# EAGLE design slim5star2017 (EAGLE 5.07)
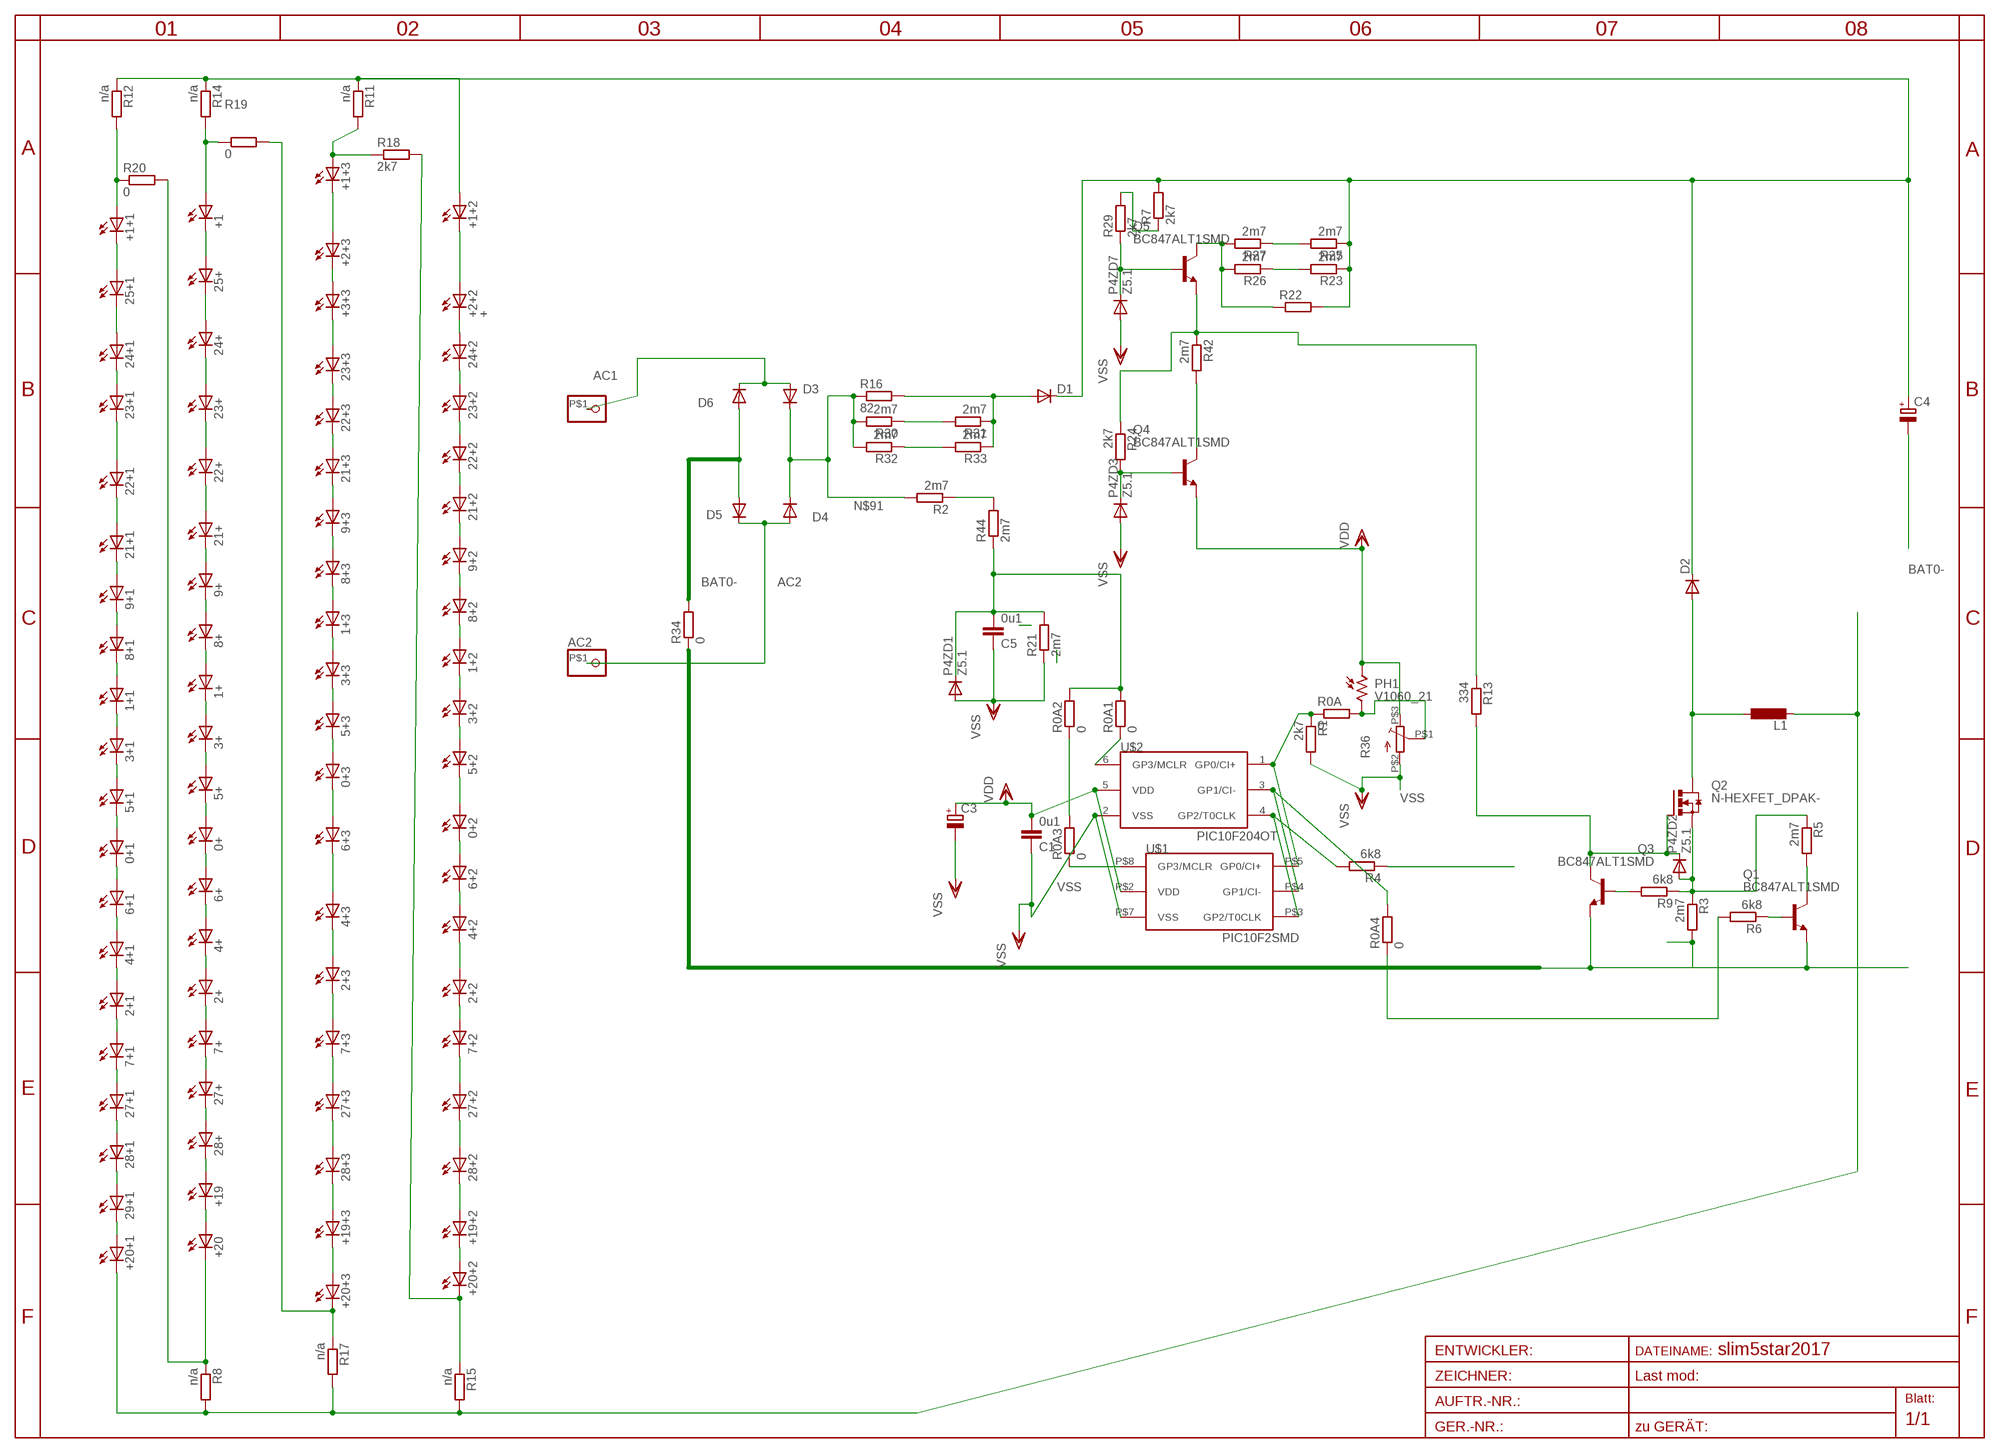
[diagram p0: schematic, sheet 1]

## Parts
0+  LED1210  [1210]
0+1  LED1210  [1210]
0+2  LED1210  [1210]
0+3  LED1210  [1210]
1+  LED1210  [1210]
1+1  LED1210  [1210]
1+2  LED1210  [1210]
1+3  LED1210  [1210]
2+  LED1210  [1210]
2+1  LED1210  [1210]
2+2  LED1210  [1210]
2+3  LED1210  [1210]
3+  LED1210  [1210]
3+1  LED1210  [1210]
3+2  LED1210  [1210]
3+3  LED1210  [1210]
4+  LED1210  [1210]
4+1  LED1210  [1210]
4+2  LED1210  [1210]
4+3  LED1210  [1210]
5+  LED1210  [1210]
5+1  LED1210  [1210]
5+2  LED1210  [1210]
5+3  LED1210  [1210]
6+  LED1210  [1210]
6+1  LED1210  [1210]
6+2  LED1210  [1210]
6+3  LED1210  [1210]
7+  LED1210  [1210]
7+1  LED1210  [1210]
7+2  LED1210  [1210]
7+3  LED1210  [1210]
8+  LED1210  [1210]
8+1  LED1210  [1210]
8+2  LED1210  [1210]
8+3  LED1210  [1210]
9+  LED1210  [1210]
9+1  LED1210  [1210]
9+2  LED1210  [1210]
9+3  LED1210  [1210]
21+  LED1210  [1210]
21+1  LED1210  [1210]
21+2  LED1210  [1210]
21+3  LED1210  [1210]
22+  LED1210  [1210]
22+1  LED1210  [1210]
22+2  LED1210  [1210]
22+3  LED1210  [1210]
23+  LED1210  [1210]
23+1  LED1210  [1210]
23+2  LED1210  [1210]
23+3  LED1210  [1210]
24+  LED1210  [1210]
24+1  LED1210  [1210]
24+2  LED1210  [1210]
25+  LED1210  [1210]
25+1  LED1210  [1210]
27+  LED1210  [1210]
27+1  LED1210  [1210]
27+2  LED1210  [1210]
27+3  LED1210  [1210]
28+  LED1210  [1210]
28+1  LED1210  [1210]
28+2  LED1210  [1210]
28+3  LED1210  [1210]
29+1  LED1210  [1210]
+1  LED1210  [1210]
+1+1  LED1210  [1210]
+1+2  LED1210  [1210]
+1+3  LED1210  [1210]
+2+2  +  LED1210  [1210]
+2+3  LED1210  [1210]
+3+3  LED1210  [1210]
+19  LED1210  [1210]
+19+2  LED1210  [1210]
+19+3  LED1210  [1210]
+20  LED1210  [1210]
+20+1  LED1210  [1210]
+20+2  LED1210  [1210]
+20+3  LED1210  [1210]
AC1  PINHD-1X1SMD  [SMD1X1]
AC2  PINHD-1X1SMD  [SMD1X1]
C1  0u1  C-EUC1206  [C1206]
C3  CPOL-EUE  [PANASONIC_E]
C4  CPOL-EUSANYO_SMD_F12  [SANYO-OSCON_SMD_F12]
C5  0u1  C-EUC1206  [C1206]
D1  DIODE-SMA-DO214  [SMA-DO214AC]
D2  DIODE-SMC  [SMC]
D3  DIODE-SOD80C  [SOD80C]
D4  DIODE-SOD80C  [SOD80C]
D5  DIODE-SOD80C  [SOD80C]
D6  DIODE-SOD80C  [SOD80C]
L1  L-EUPIS2816  [PIS2816]
P4ZD1  Z5.1  DIODE-MINIMELF  [MINIMELF]
P4ZD2  Z5.1  DIODE-MINIMELF  [MINIMELF]
P4ZD3  Z5.1  DIODE-MINIMELF  [MINIMELF]
P4ZD7  Z5.1  DIODE-MINIMELF  [MINIMELF]
PH1  V1060_21  [TO-5_V10]
Q1  BC847ALT1SMD  [SOT23]
Q2  N-HEXFET_DPAK-  [TO252]
Q3  BC847ALT1SMD  [SOT23]
Q4  BC847ALT1SMD  [SOT23]
Q5  BC847ALT1SMD  [SOT23]
R0A  0  R-EU_R1206  [R1206]
R0A1  0  R-EU_R1206  [R1206]
R0A2  0  R-EU_R1206  [R1206]
R0A3  0  R-EU_R1206  [R1206]
R0A4  0  R-EU_R1206  [R1206]
R1  2k7  R-EU_R0805  [R0805]
R2  2m7  R-EU_R1210  [R1210]
R3  2m7  R-EU_R1206  [R1206]
R4  6k8  R-EU_R0805  [R0805]
R5  2m7  R-EU_R1210  [R1210]
R6  6k8  R-EU_R1206  [R1206]
R7  2k7  R-EU_R0805  [R0805]
R8  n/a  R-EU_R0402  [R0402]
R9  6k8  R-EU_R1206  [R1206]
R11  n/a  R-EU_R0402  [R0402]
R12  n/a  R-EU_R0402  [R0402]
R13  334  R-EU_R0805  [R0805]
R14  n/a  R-EU_R0402  [R0402]
R15  n/a  R-EU_R0402  [R0402]
R16  82  R-EU_SMD15  [SMDCARB15]
R17  n/a  R-EU_R0402  [R0402]
R18  2k7  R-EU_R0402  [R0402]
R19  0  R-EU_R0402  [R0402]
R20  0  R-EU_R0402  [R0402]
R21  2m7  R-EU_R0805  [R0805]
R22  R-EU_SMD15  [SMDCARB15]
R23  2m7  R-EU_R1210  [R1210]
R24  2k7  R-EU_R1206  [R1206]
R25  2m7  R-EU_R1210  [R1210]
R26  2m7  R-EU_R1210  [R1210]
R27  2m7  R-EU_R1210  [R1210]
R29  2k7  R-EU_R0805  [R0805]
R30  2m7  R-EU_R1210  [R1210]
R31  2m7  R-EU_R1210  [R1210]
R32  2m7  R-EU_R1210  [R1210]
R33  2m7  R-EU_R1210  [R1210]
R34  0  R-EU_R1206  [R1206]
R36  TRIM_EU-SMD6A  [CA6VSMD]
R42  2m7  R-EU_R1206  [R1206]
R44  2m7  R-EU_R1210  [R1210]
U$1  PIC10F2SMD  [DIL8SMD]
U$2  PIC10F204OT  [SOT23-6]

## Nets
AC1: Q5.2(E) R13.1 R24.1 R42.1
AC2: AC2.P$1 D4.A D5.C
BAT0-: C4.- D5.A D6.A R34.2
BATT-: Q1.2(E) Q3.2(E) R3.2 R34.1
D: D2.A L1.1 Q2.3(D)
D+: +1+2.P$1(A) C4.+ D1.K(C) D2.C R7.2 R11.1 R12.1 R14.1 R22.P$2 R23.1 R25.1
MINUS: +20+1.P$2(C) L1.2 R8.2 R15.2 R17.2
N$1: +1+3.P$1(A) R11.2 R18.1
N$2: +1+1.P$1(A) R12.2 R20.1
N$4: +20+3.P$2(C) R17.1 R19.2
N$5: Q4.3(C) R42.2
N$6: 8+.P$1(A) 9+.P$2(C)
N$7: +19.P$2(C) +20.P$1(A)
N$8: 28+.P$2(C) +19.P$1(A)
N$9: 27+.P$2(C) 28+.P$1(A)
N$10: 29+1.P$2(C) +20+1.P$1(A)
N$11: 28+1.P$2(C) 29+1.P$1(A)
N$12: 2+.P$2(C) 7+.P$1(A)
N$13: 7+.P$2(C) 27+.P$1(A)
N$14: 2+.P$1(A) 4+.P$2(C)
N$15: 4+.P$1(A) 6+.P$2(C)
N$16: 0+.P$2(C) 6+.P$1(A)
N$17: 0+.P$1(A) 5+.P$2(C)
N$18: 3+.P$2(C) 5+.P$1(A)
N$19: 1+.P$2(C) 3+.P$1(A)
N$20: 1+.P$1(A) 8+.P$2(C)
N$21: 27+1.P$2(C) 28+1.P$1(A)
N$22: 2+1.P$1(A) 4+1.P$2(C)
N$23: 9+.P$1(A) 21+.P$2(C)
N$24: 21+.P$1(A) 22+.P$2(C)
N$25: 22+.P$1(A) 23+.P$2(C)
N$26: 24+.P$1(A) 25+.P$2(C)
N$27: 25+.P$1(A) +1.P$2(C)
N$28: 23+.P$1(A) 24+.P$2(C)
N$29: 4+1.P$1(A) 6+1.P$2(C)
N$30: 0+1.P$2(C) 6+1.P$1(A)
N$31: 0+1.P$1(A) 5+1.P$2(C)
N$32: 3+1.P$2(C) 5+1.P$1(A)
N$33: 1+1.P$2(C) 3+1.P$1(A)
N$34: 1+1.P$1(A) 8+1.P$2(C)
N$35: 9+1.P$1(A) 21+1.P$2(C)
N$36: 21+1.P$1(A) 22+1.P$2(C)
N$37: 22+1.P$1(A) 23+1.P$2(C)
N$38: 25+1.P$1(A) +1+1.P$2(C)
N$39: 24+1.P$1(A) 25+1.P$2(C)
N$40: 23+1.P$1(A) 24+1.P$2(C)
N$41: 2+1.P$2(C) 7+1.P$1(A)
N$42: 7+1.P$2(C) 27+1.P$1(A)
N$43: 8+1.P$1(A) 9+1.P$2(C)
N$45: +1.P$1(A) R14.2 R19.1
N$46: +19+2.P$2(C) +20+2.P$1(A)
N$47: 28+2.P$2(C) +19+2.P$1(A)
N$48: 27+2.P$2(C) 28+2.P$1(A)
N$49: 2+2.P$1(A) 4+2.P$2(C)
N$50: 4+2.P$1(A) 6+2.P$2(C)
N$51: 0+2.P$2(C) 6+2.P$1(A)
N$52: 0+2.P$1(A) 5+2.P$2(C)
N$53: 3+2.P$2(C) 5+2.P$1(A)
N$54: 1+2.P$2(C) 3+2.P$1(A)
N$55: 1+2.P$1(A) 8+2.P$2(C)
N$56: 9+2.P$1(A) 21+2.P$2(C)
N$57: 21+2.P$1(A) 22+2.P$2(C)
N$58: 22+2.P$1(A) 23+2.P$2(C)
N$59: +1+2.P$2(C) +2+2.P$1(A)
N$60: 24+2.P$1(A) +2+2.P$2(C)
N$61: 23+2.P$1(A) 24+2.P$2(C)
N$62: 2+2.P$2(C) 7+2.P$1(A)
N$63: 7+2.P$2(C) 27+2.P$1(A)
N$64: 8+2.P$1(A) 9+2.P$2(C)
N$65: +20+2.P$2(C) R15.1 R18.2
N$66: +20.P$2(C) R8.1 R20.2
N$67: +19+3.P$2(C) +20+3.P$1(A)
N$68: 28+3.P$2(C) +19+3.P$1(A)
N$69: 27+3.P$2(C) 28+3.P$1(A)
N$70: 2+3.P$1(A) 4+3.P$2(C)
N$71: 4+3.P$1(A) 6+3.P$2(C)
N$72: 0+3.P$2(C) 6+3.P$1(A)
N$73: 0+3.P$1(A) 5+3.P$2(C)
N$74: 3+3.P$2(C) 5+3.P$1(A)
N$75: 1+3.P$2(C) 3+3.P$1(A)
N$76: 1+3.P$1(A) 8+3.P$2(C)
N$77: 9+3.P$1(A) 21+3.P$2(C)
N$78: 21+3.P$1(A) 22+3.P$2(C)
N$79: 22+3.P$1(A) 23+3.P$2(C)
N$80: +1+3.P$2(C) +2+3.P$1(A)
N$81: +2+3.P$2(C) +3+3.P$1(A)
N$82: 23+3.P$1(A) +3+3.P$2(C)
N$83: 2+3.P$2(C) 7+3.P$1(A)
N$84: 7+3.P$2(C) 27+3.P$1(A)
N$85: 8+3.P$1(A) 9+3.P$2(C)
N$86: D1.A R16.P$2 R31.1 R33.1
N$88: PH1.2 R0A.2 R36.P$1(S)
N$91: D3.C D4.C R2.2 R16.P$1 R30.2 R32.2
N$92: Q5.3(C) R22.P$1 R26.2 R27.2
N$93: AC1.P$1 D3.A D6.C
N$94: P4ZD2.C Q2.1(G) Q3.3(C) R13.2
N$95: R4.2 U$1.P$3(GP2/T0CLK) U$2.4(GP2/T0CLK)
N$96: C5.2 P4ZD1.C R0A1.2 R0A2.2 R21.2 R44.1
N$97: R2.1 R44.2
N$98: Q1.1(B) R6.1
N$99: R23.2 R26.1
N$100: R25.2 R27.1
N$101: Q1.3(C) R5.2
N$102: R0A4.1 R6.2
N$103: P4ZD3.C Q4.1(B) R24.2
N$104: P4ZD7.C Q5.1(B) R29.1
N$105: P4ZD2.A Q2.2(S) R3.1 R5.1 R9.1
N$106: R7.1 R29.2
N$107: R30.1 R31.2
N$108: R32.1 R33.2
N$109: Q3.1(B) R9.2
N$110: R0A.1 R1.1 U$1.P$5(GP0/CI+) U$2.1(GP0/CI+)
N$111: R0A2.1 R0A3.2
N$112: R0A3.1 U$1.P$8(GP3/MCLR)
N$113: R0A1.1 U$2.6(GP3/MCLR)
N$114: R0A4.2 U$1.P$4(GP1/CI-) U$2.3(GP1/CI-)
PIR: R4.1
VDD: C1.2 C3.+ PH1.1 Q4.2(E) R36.P$3(E) U$1.P$2(VDD) U$2.5(VDD)
VSS: C1.1 C3.- C5.1 P4ZD1.A P4ZD3.A P4ZD7.A R1.2 R21.1 R36.P$2(A) U$1.P$7(VSS) U$2.2(VSS)

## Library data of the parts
0+ 0+1-0+3 1+ 1+1-1+3 2+ 2+1-2+3 3+ 3+1-3+3 4+ 4+1-4+3 5+ 5+1-5+3 6+ 6+1-6+3 7+ 7+1-7+3 8+ 8+1-8+3 9+ 9+1-9+3 21+ 21+1-21+3 22+ 22+1-22+3 23+ 23+1-23+3 24+ 24+1 24+2 25+ 25+1 27+ 27+1-27+3 28+ 28+1-28+3 29+1 +1 +1+1-+1+3 +2+2 +2+3 +3+3 +19 +19+2 +19+3 +20 +20+1-+20+3 = led(2):LED: LED
AC1 AC2 = pinhead:PINHD-1X1: PIN HEADER
C1 C5 = rcl:C-EU: CAPACITOR, European symbol
C3 C4 = rcl-2:CPOL-EU: POLARIZED CAPACITOR, European symbol
D1-D6 P4ZD1-P4ZD3 P4ZD7 = diode:DIODE-: DIODE
L1 = rcl:L-EU: INDUCTOR, European symbol
PH1 = photo-elements:?1060*: Sensor Street Light control
Q1 Q3-Q5 = transistor-npn:BC847*: NPN Transistor
Q2 = transistor-power:N-HEXFET_?-*: HEXFET® Power MOSFET
R0A R0A1-R0A4 R1-R7 R9 R13 R16 R21-R23 R25-R27 R29-R34 R42 R44 = rcl:R-EU_: RESISTOR, European symbol
R8 R11 R12 R14 R15 R17-R20 R24 = rcl-2:R-EU_: RESISTOR, European symbol
R36 = pot:TRIM_EU-: POTENTIOMETER
U$1 U$2 = microchip-5:PIC10F2*: uPC nW 0,25/0,5k Program Flash memory Comparator

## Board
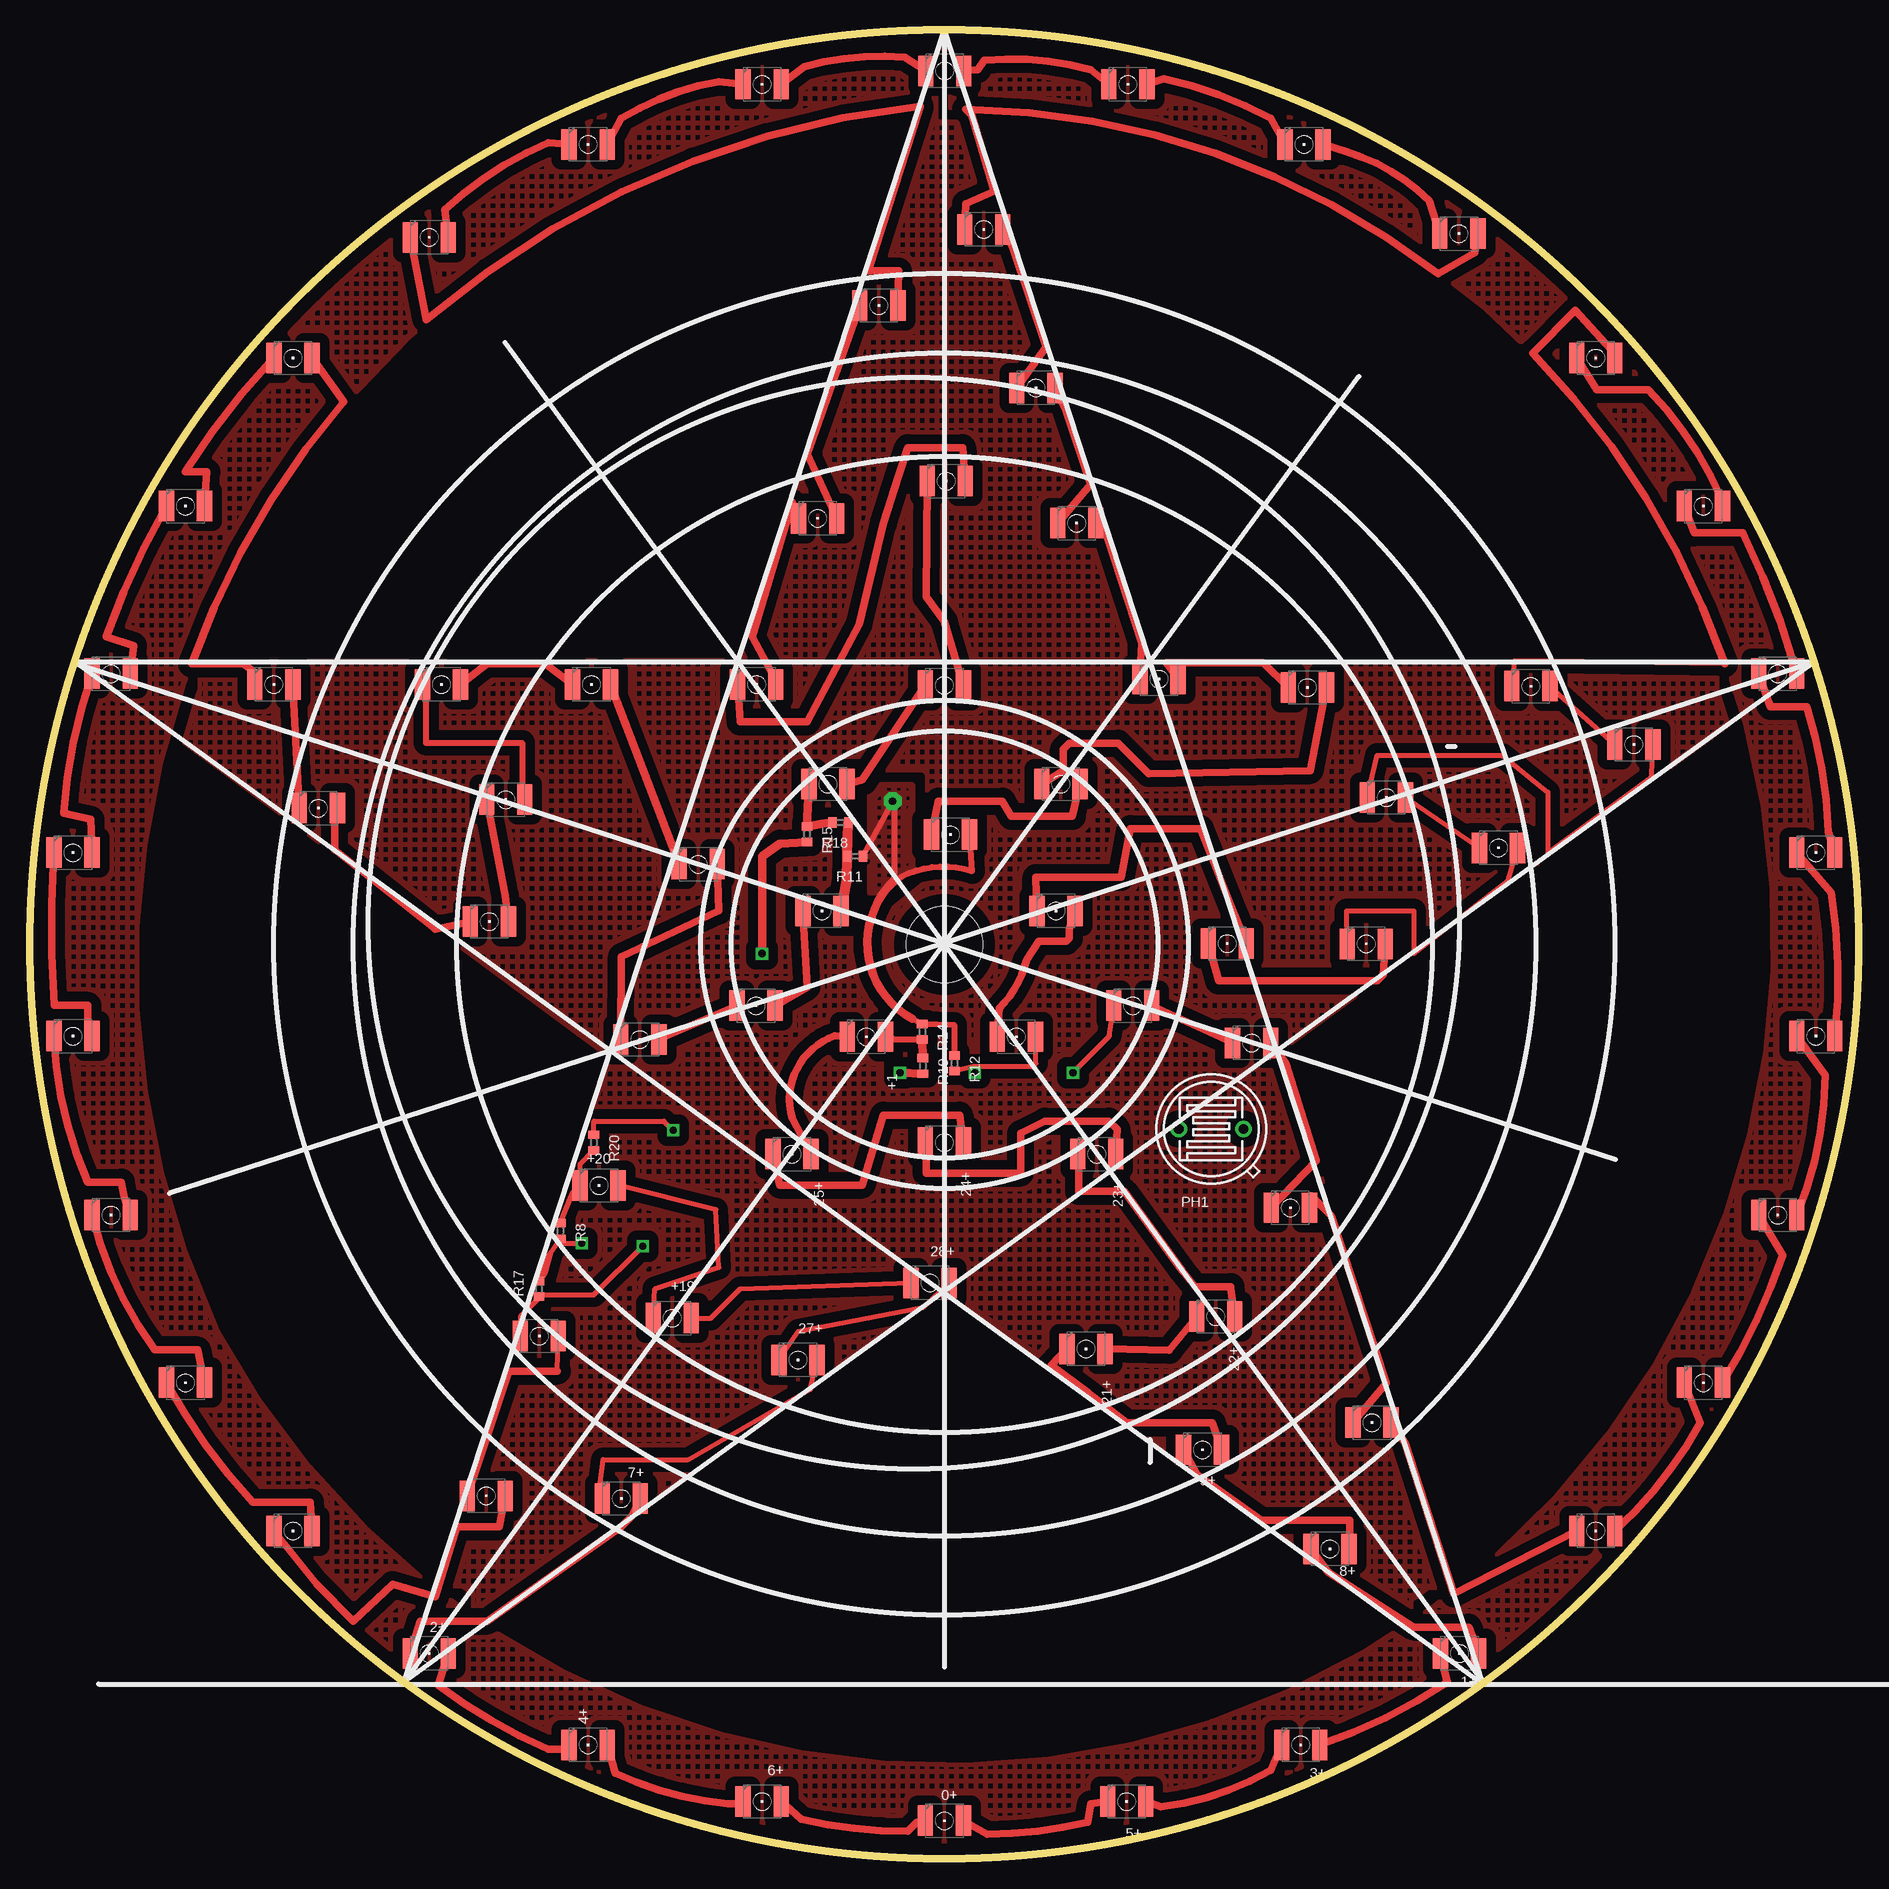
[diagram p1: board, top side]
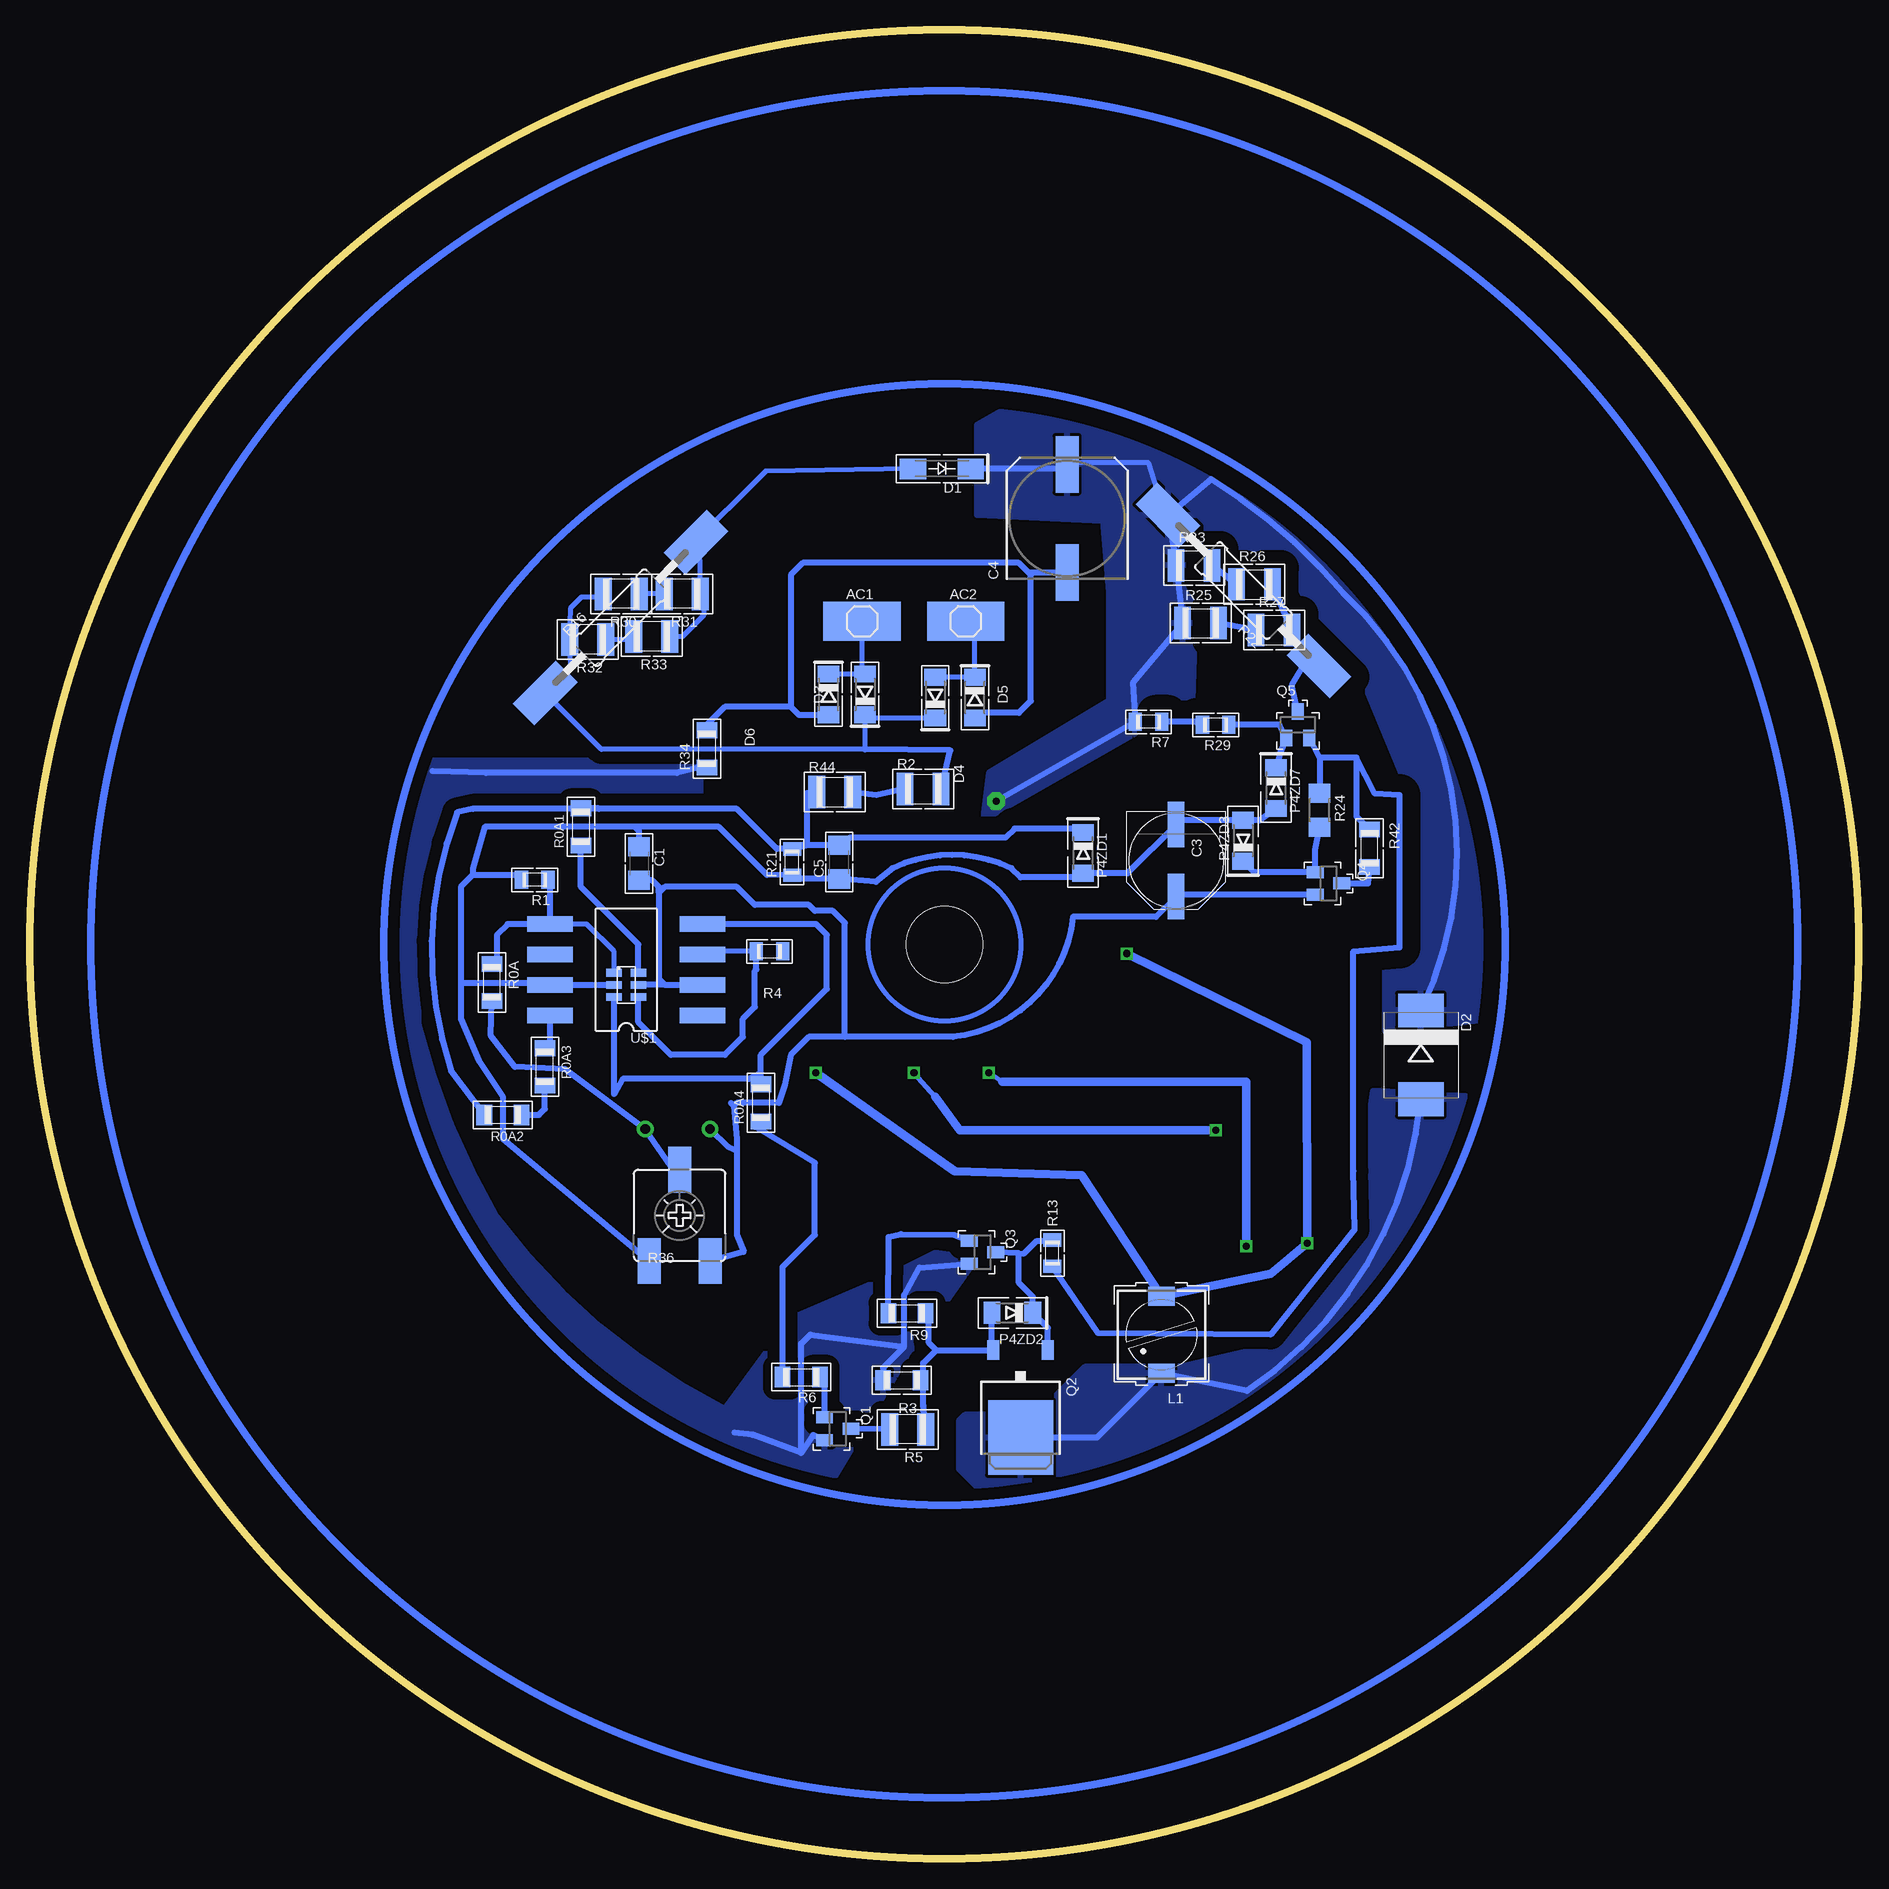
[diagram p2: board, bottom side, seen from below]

Size 152.4 x 152.4 mm. Coordinates in mm from the lower left corner, seen from the top.
Outline: circle at 76.2,76.2 radius 76.2
Copper layers (1*16): Top 0.035mm / dielectric 1.5mm / Bottom 0.035mm
Design rules "default": minimum track width 10mil, minimum drill 24mil, track to track 8mil, track to pad 8mil, pad to pad 8mil, via to via 8mil, smd to smd 8mil, copper to edge 40mil, drill to drill 8mil, minimum pad ring 10mil, minimum via ring 8mil, stop-mask expansion 4mil, vias tented up to drill 0mil, thermal gap 10mil
Holes 6.35 mm at 76.2,76.2

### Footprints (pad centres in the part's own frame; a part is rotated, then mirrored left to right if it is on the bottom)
1210 = smd 1.27 x 2.54: P$1 1.587,0; P$2 -1.587,0
SMD1X1 = smd 6.452 x 3.251: P$1 0,0
C1206 = smd 1.6 x 1.8: 1 -1.4,0; 2 1.4,0
PANASONIC_E = smd 3.8 x 1.4: + 3,0; - -3,0
SANYO-OSCON_SMD_F12 = smd 4.7 x 1.9: + 4.5,0; - -4.5,0
SMA-DO214AC = smd 2.2 x 1.7: A 2.4,0; K -2.4,0
SMC = smd 2.8 x 3.8: A 3.7,0; C -3.7,0
SOD80C = smd 1.4 x 1.8: A 1.7,0; C -1.7,0
PIS2816 = smd 2.2 x 1.6: 1 0,3.2; 2 0,-3.2
MINIMELF = smd 1.4 x 1.8: A 1.7,0; C -1.7,0
TO-5_V10 = drill 0.8 pad 1.4 round: 1 -2.7,0; 2 2.7,0
SOT23 = smd 1 x 1.4: 1 -0.95,-1.1; 2 0.95,-1.1; 3 0,1.1
TO252 = smd 1 x 1.6: 1 -2.28,-3.53; 2 2.28,-3.53 | smd 5.4 x 6.2: 3 0,3.77
R1206 = smd 1.3 x 1.7: 1 -1.55,0; 2 1.55,0
R0805 = smd 1.1 x 1.5: 1 -1.1,0; 2 1.1,0
R1210 = smd 1.4 x 2.7: 1 -1.5,0; 2 1.5,0
R0402 = smd 0.7 x 0.9: 1 -0.65,0; 2 0.65,0
SMDCARB15 = smd 5.08 x 2.54: P$1 -8.89,0; P$2 8.89,0
R1206' = smd 1.6 x 1.803: 1 -1.422,0; 2 1.422,0
CA6VSMD = smd 1.93 x 3.81: P$1 0,3.81; P$2 -2.54,-3.81; P$3 2.54,-3.81
DIL8SMD = smd 1.27 x 3.81: P$1 -3.81,-6.35; P$2 -1.27,-6.35; P$3 1.27,-6.35; P$4 3.81,-6.35; P$5 3.81,6.35; P$6 1.27,6.35; P$7 -1.27,6.35; P$8 -3.81,6.35
SOT23-6 = smd 0.635 x 1.27: 1 -1.016,-1.016; 2 0,-1.016; 3 1.016,-1.016; 4 1.016,1.016; 5 0,1.016; 6 -1.016,1.016

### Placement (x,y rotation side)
0+  76.2,3.17 0 top
0+1  148.82,83.85 0 top
0+2  61.01,147.88 0 top
0+3  12.95,112.73 0 top
1+  119.13,17.12 0 top
1+1  130.48,125.07 0 top
1+2  106.17,142.88 0 top
1+3  24.03,87.55 0 top
2+  33.27,17.12 0 top
2+1  139.45,39.67 0 top
2+2  70.74,129.44 0 top
2+3  3.58,68.55 0 top
3+  105.89,9.5 0 top
3+1  139.45,112.73 0 top
3+2  91.49,147.88 0 top
3+3  20.32,97.87 0 top
4+  46.51,9.5 0 top
4+1  145.64,53.64 0 top
4+2  33.27,135.13 0 top
4+3  3.58,83.85 0 top
5+  91.39,4.78 0 top
5+1  145.64,98.76 0 top
5+2  76.23,149 0 top
5+3  21.92,125.07 0 top
6+  61.01,4.78 0 top
6+1  148.82,68.55 0 top
6+2  46.51,142.88 0 top
6+3  6.76,98.76 0 top
7+  49.28,30.02 0 top
7+1  130.48,27.33 0 top
7+2  65.63,111.71 0 top
7+3  6.76,53.64 0 top
8+  108.33,25.83 0 top
8+1  125.07,97.71 0 top
8+2  119.08,135.43 0 top
8+3  38.28,78.11 0 top
9+  97.71,34.09 0 top
9+1  133.65,92.86 0 top
9+2  79.48,135.79 0 top
9+3  39.65,88.27 0 top
21+  88,42.5 0 top
21+1  113.03,88.44 0 top
21+2  83.82,122.58 0 top
21+3  34.29,97.87 0 top
22+  98.81,45.19 0 top
22+1  122.38,84.25 0 top
22+2  87.22,111.3 0 top
22+3  46.79,97.87 0 top
23+  88.9,58.72 0 top
23+1  111.35,76.25 0 top
23+2  94.08,98.32 0 top
23+3  55.68,82.88 0 top
24+  76.2,59.69 0 top
24+1  99.77,76.28 0 top
24+2  106.45,97.61 0 top
25+  63.5,58.72 0 top
25+1  85.5,79 0 top
27+  64,41.58 0 top
27+1  111.84,36.35 0 top
27+2  60.55,97.87 0 top
27+3  12.95,39.67 0 top
28+  75,48 0 top
28+1  105.03,54.25 0 top
28+2  76.35,114.81 0 top
28+3  21.92,27.33 0 top
29+1  101.8,68 0 top
+1  69.7,68.5 0 top
+1+1  82.19,68.5 0 top
+1+2  76.71,85.34 0 top
+1+3  66,79 0 top
+2+2  85.9,89.56 0 top
+2+3  60.5,71.09 0 top
+3+3  50.83,68.28 0 top
+19  53.52,45.06 0 top
+19+2  76.2,97.79 0 top
+19+3  38.02,30.25 0 top
+20  47.42,56.11 0 top
+20+1  91.9,71.09 0 top
+20+2  66.5,89.56 0 top
+20+3  42.44,43.56 0 top
AC1  83.06,103.12 0 bottom
AC2  74.42,103.12 0 bottom
C1  101.65,82.94 270 bottom
C3  56.9,83.19 270 bottom
C4  65.97,111.7 90 bottom
C5  84.96,83.06 90 bottom
D1  76.41,115.82 180 bottom
D2  36.5,67 270 bottom
D3  82.8,97.03 90 bottom
D4  76.96,96.77 90 bottom
D5  73.66,96.77 270 bottom
D6  85.85,97.03 270 bottom
L1  58.11,43.67 180 bottom
P4ZD1  64.64,83.82 270 bottom
P4ZD2  70.53,45.5 180 bottom
P4ZD3  51.31,84.84 90 bottom
P4ZD7  48.55,89.23 270 bottom
PH1  98.43,60.81 0 top
Q1  85.09,35.83 270 bottom
Q2  69.85,38.86 180 bottom
Q3  73.03,50.55 270 bottom
Q4  44.2,81.28 270 bottom
Q5  46.74,94.5 0 bottom
R0A  113.91,73.03 270 bottom
R0A1  106.5,86 90 bottom
R0A2  113,62 180 bottom
R0A3  109.5,66 270 bottom
R0A4  91.5,63 90 bottom
R1  110.33,81.58 180 bottom
R2  77.98,89.15 0 bottom
R3  79.76,39.88 180 bottom
R4  90.78,75.61 180 bottom
R5  79.26,35.79 180 bottom
R6  88.13,40.14 180 bottom
R7  59.19,94.74 180 bottom
R8  44.2,52.32 270 top
R9  79.32,45.47 180 bottom
R11  68.76,83.55 180 top
R12  77.04,66.29 270 top
R13  67.2,50.47 90 bottom
R14  74.36,68.93 270 top
R15  64.75,85.37 270 top
R16  103.18,103.43 45 bottom
R17  42.42,47.5 90 top
R18  67.54,86.36 180 top
R19  74.41,66.07 270 top
R20  46.99,59.69 270 top
R21  88.9,83.06 90 bottom
R22  51.28,105.68 135 bottom
R23  55.39,107.78 0 bottom
R24  2k7  [R1206']  44.93,87.38 270 bottom
R25  54.85,102.97 0 bottom
R26  50.37,106.21 0 bottom
R27  48.73,102.4 0 bottom
R29  53.59,94.49 180 bottom
R30  103.12,105.41 180 bottom
R31  98.04,105.41 180 bottom
R32  105.92,101.6 180 bottom
R33  100.58,101.85 180 bottom
R34  96,92.5 90 bottom
R36  98.27,53.62 0 bottom
R42  40.77,84.21 270 bottom
R44  85.34,88.9 0 bottom
U$1  102.71,74.09 90 bottom
U$2  102.71,72.82 270 bottom

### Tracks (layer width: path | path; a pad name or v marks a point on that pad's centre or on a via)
AC1
  Bottom 0.5: R13.1 63.39,43.8 49.01,43.68 42.01,52.45 42.12,57.33 42.12,75.62 38.27,75.95 38.27,88.65 40.32,88.76 41.87,91.76 | 41.87,91.76 44.94,91.76 | 44.94,91.76 Q5.2 | R42.1 41.87,86.86 41.87,91.76 | R24.1 44.94,91.76
AC2
  Bottom 0.406: AC2.P$1 73.66,103.12 D5.C D4.A
BAT0-
  Bottom 0.5: D6.A 88.33,95.33 89,96 | 89,96 89,107 88,108 70,108 69.2,107.2 | 69.2,107.2 69,107 69,96.5 70,95.5 73.23,95.5 D5.A | 69.2,107.2 C4.- | 89,96 94.5,96 96,94.5 R34.2
BATT-
  Bottom 0.5: Q3.2 78.29,49.26 79.57,46.98 79.57,42.68 | 79.57,42.68 81.31,40.92 R3.2 | Q1.2 87.13,35.32 88.13,33.82 | 88.13,33.82 88.13,42.93 87.38,43.68 79.57,42.68 | R34.1 96.55,90.95 98.5,90.5 114.4,90.5 118.84,90.64 | 88.13,33.82 92.19,35.32 93.7,35.51
  pour Bottom (isolate 1): 96.5,91.5 120.5,91.5 123.5,72.5 116.5,51.5 98.5,34.5 85.5,31.5 79.5,41.5 73.5,50 77,50.5 82,48 89,45 94.5,37.5 arc26 113.5,53.5 arc16 120,69.5 arc16 117.5,88 96.5,88
D
  Bottom 0.5: D2.A arc51 51,39 L1.1 63.49,35.09 Q2.3
  pour Bottom (isolate 1): 58,41 64.5,41 68.5,37 74.5,37 75,36.5 75,32.5 73.5,31 59,33 41.5,44.5 32,63.5 40.5,64 42,53.5 50,42.5 56.5,41
D+  (via drill 0.6 pad 1.5)
  Top 0.5: R11.1 v71.88,88.14 72,88.02 72,81.5 arc-51 78.5,82.3 +1+2.P$1 | 73.5,70 R14.1 77,69.5 R12.1
  Top 0.7: 72,81.5 arc107 73.5,70
  Bottom 0.406: R22.P$2 57.82,111.97 59.18,116.33 65.84,116.33 C4.+
  Bottom 0.5: v71.88,88.14 R7.2 60.5,98 R25.1 R23.1 R22.P$2 53.97,114.97 arc18 43,105.5 arc73 D2.C | D1.K 66.35,115.82 C4.+
  pour Bottom (isolate 1.5): 30.5,70 32,92 44,110.5 59,119 70,121.5 73.5,119.5 73.5,112 63,111.5 62.5,105.5 62.5,96.5 72.5,90.5 73,86.5 55.5,96.5 55,111 42.5,101 36.5,86.5 37,75 39.5,74 39.5,69
  pour Top (isolate 1, hatched): 70,89.5 73.5,89.5 73.5,82.5 71,80.5 70,80.5
MINUS  (via drill 0.6)
  Top 0.406: 43.32,50.43 R17.2 42.93,48.77 43.43,50.55 R8.2 44.56,51.31 v45.97,51.31 | +20+1.P$2 89.94,68.56 v86.92,65.5
  Top 0.7: R15.2 62.49,84.59 61,83.57 v61,75.44
  Bottom 0.7: v61,75.44 46.02,68.06 v45.97,51.31 49.02,48.77 L1.2 64.74,56.97 75.35,57.28 v86.92,65.5
N$1
  Top 0.813: R18.1 R11.2 68.07,81.5 +1+3.P$1
N$2  (via drill 0.6)
  Top 0.406: 78.74,66.04 R12.2 | 78.74,66.04 83.57,66.04 83.82,66.29 83.82,68.47 +1+1.P$1 | R20.1 46.99,61.47 52.83,61.47 v53.59,60.71 | v78.74,65.5 78.74,66.04
  Bottom 0.406: 76.96,63.5 v78.74,65.5
  Bottom 0.7: v53.59,60.71 74.93,60.71 76.96,63.5
N$3
  pour Top (isolate 0.813, rank 2, hatched): 48.31,66.78 31.24,14.66 76.33,47.45 120.95,14.66 104.27,67.36 148.74,99.77 93.29,99.72 76.2,152.4 59.18,99.87 3.76,99.75
N$4  (via drill 0.6)
  Top 0.406: 42.53,46.85 R17.1 | 42.53,46.85 40.89,45.21 40.89,43.6 +20+3.P$2 | 42.53,46.85 42.67,46.99 46.99,46.99 v51.05,51.05
  Top 0.7: v72.5,65.5 R19.2
  Bottom 0.406: 71.39,64.77 v72.5,65.5
  Bottom 0.7: v51.05,51.05 51.05,64.77 71.39,64.77
N$5
  Bottom 0.5: Q4.3 40.89,81.28 R42.2
N$6
  Top 0.61: 8+.P$1 109.98,28.19 102.62,28.19 97.28,32 9+.P$2
N$7
  Top 0.406: +19.P$2 52.07,47.5 57.4,49.28 57.15,54.1 +20.P$1
N$8
  Top 0.406: +19.P$1 56.74,45.06 59.18,47.5 28+.P$2
N$9
  Top 0.406: 28+.P$1 74.43,45.98 64.01,43.94 27+.P$2
N$10
  Top 0.61: +20+1.P$1 29+1.P$2
N$11
  Top 0.61: 28+1.P$2 107.19,58.17 104.65,66.29 29+1.P$1
N$12
  Top 0.61: 7+.P$1 50.1,28.51 49.28,27.69 38.1,19.81 32.51,19.81 2+.P$2
N$13
  Top 0.406: 27+.P$1 65.02,39.12 54.86,33.27 47.75,33.27 47.5,30.99 47.75,30.99 48.01,30.48 7+.P$2
N$14
  Top 0.61: 2+.P$1 34.04,14.48 arc14 43.18,9.14 44.92,9.14 4+.P$2
N$15
  Top 0.61: 4+.P$1 48.77,7.11 arc19 58.17,4.57 59.22,4.57 6+.P$2
N$16
  Top 0.61: 6+.P$1 64.26,3.3 arc13 73.15,2.29 73.91,3.05 0+.P$2
N$17
  Top 0.61: 0+.P$1 79.76,2.03 arc13 88.14,3.05 88.39,4.57 5+.P$2
N$18
  Top 0.61: 5+.P$1 94.23,4.32 arc23 103.38,7.37 3+.P$2
N$19
  Top 0.61: 3+.P$1 arc16 118.11,14.73 1+.P$2
N$20
  Top 0.61: 1+.P$1 119.89,19.3 115.32,19.3 108.2,23.88 8+.P$2
N$21
  Top 0.61: 27+1.P$2 113.03,39.62 108.46,53.59 106.78,55.27 28+1.P$1
N$22
  Top 0.61: 4+1.P$2 146.05,50.29 arc-13 2+1.P$1
N$23
  Top 0.61: 9+.P$1 98.54,36.34 91.4,36.34 88.1,38.88 88.14,38.86 85.09,41.15 21+.P$2
N$24
  Top 0.61: 21+.P$1 94.96,42.37 22+.P$2
N$25
  Top 0.61: 22+.P$1 100.08,47.5 100.08,47.69 97.09,47.69 96.01,49.02 91.19,55.63 87.38,55.63 87.38,58.81 23+.P$2
N$26
  Top 0.61: 25+.P$2 62.48,56.13 69.34,56.13 71.12,61.98 77.47,61.98 24+.P$1
N$27
  Top 0.61: +1.P$2 67.06,68.58 arc86 63.5,61.72 25+.P$1
N$28
  Top 0.61: 23+.P$1 90.59,60.8 89.92,61.47 84.58,61.47 82.55,60.45 82.55,57.15 74.68,57.15 74.68,58.74 24+.P$2
N$29
  Top 0.61: 6+1.P$2 149.61,65.28 arc-22 4+1.P$1
N$30
  Top 0.61: 0+1.P$2 150.11,80.52 arc-15 6+1.P$1
N$31
  Top 0.61: 5+1.P$2 145.03,96.01 148.08,96.01 arc-15 149.86,85.6 0+1.P$1
N$32
  Top 0.61: 3+1.P$2 138.68,110.49 142.75,110.49 arc-10 147.07,99.31 5+1.P$1
N$33
  Top 0.61: 1+1.P$2 130.56,122.43 134.87,122.43 arc-21 140.97,113.28 3+1.P$1
N$34
  Top 0.406: 8+1.P$2 123.7,99.82 141.22,99.57
  Top 0.61: 141.22,99.57 arc25 125.22,125.48 128.78,129.03 131.32,126.24 131.83,125.73 1+1.P$1
N$35
  Top 0.406: 9+1.P$1 135.13,90.17 126.49,83.82 126.49,88.9 122.68,91.95 112.27,91.95 21+1.P$2
N$36
  Top 0.406: 21+1.P$1 22+1.P$2
N$37
  Top 0.406: 22+1.P$1 123.19,81.53 115.32,75.44 115.32,78.99 109.73,78.99 23+1.P$2
N$38
  Top 0.61: +1+1.P$2 80.77,70.87 arc31 83.06,74.93 84.07,76.45 86.36,76.45 86.61,76.71 86.61,77.47 25+1.P$1
N$39
  Top 0.61: 25+1.P$2 83.82,81.79 90.93,81.79 91.69,85.85 97.54,85.85 24+1.P$1
N$40
  Top 0.61: 24+1.P$2 99.06,73.15 112.27,73.15 112.78,73.66 23+1.P$1
N$41
  Top 0.61: 2+1.P$2 139.19,36.32 arc-19 7+1.P$1
N$42
  Top 0.61: 7+1.P$2 118.65,22.07 114.61,34.64 27+1.P$1
N$43
  Top 0.406: 8+1.P$1 9+1.P$2
N$44
  pour Top (isolate 0.813, hatched): 76.73,152.45 arc-78 150.27,90.47 arc-83 103.84,5.31 arc-84 9.42,40.97 arc-114 75.54,152.35 74.55,145.8 arc110 15.49,44.2 arc241 76.73,145.82
N$45
  Top 0.406: +1.P$1 71.5,68.72
  Top 0.5: 71.5,68.72 71.95,68.28 R14.2
  Top 0.7: R14.2 R19.1
N$46
  Top 0.61: +19+2.P$2 69.34,89.92 +20+2.P$1
N$47
  Top 0.61: +19+2.P$1 76.2,103.12 74.68,105.16 28+2.P$2
N$48
  Top 0.61: 27+2.P$2 59.18,94.74 64.77,94.74 69.09,102.87 71.12,111.25 72.39,115.32 73.15,117.6 77.72,117.6 28+2.P$1
N$49
  Top 0.61: 4+2.P$2 33.02,128.27 arc-34 74.17,146.07 69.85,132.33 72.39,132.33 2+2.P$1
N$50
  Top 0.61: 4+2.P$1 34.54,137.41 arc-20 43.18,143 6+2.P$2
N$51
  Top 0.61: 6+2.P$1 49.28,145.03 arc-23 57.4,148.08 0+2.P$2
N$52
  Top 0.61: 0+2.P$1 64.52,149.35 arc-20 72.9,150.11 5+2.P$2
N$53
  Top 0.61: 5+2.P$1 78.99,149.1 79.5,149.86 arc-21 88.39,149.1 3+2.P$2
N$54
  Top 0.61: 3+2.P$1 94.49,148.34 arc-17 103.38,145.03 1+2.P$2
N$55
  Top 0.61: 1+2.P$1 109.73,142.24 arc-29 116.59,138.18 8+2.P$2
N$56
  Top 0.61: 21+2.P$2 84.69,125.99 81.92,134.17 9+2.P$1
N$57
  Top 0.61: 22+2.P$2 88.39,114.55 86.36,120.65 21+2.P$1
N$58
  Top 0.61: 23+2.P$2 92.65,101.33 89.82,110.06 22+2.P$1
N$59
  Top 0.61: +1+2.P$2 75.69,88.14 81.03,88.14 81.79,86.87 86.87,86.87 +2+2.P$1
N$60
  Top 0.61: +2+2.P$2 86.11,90.68 86.11,92.46 86.61,92.96 90.68,92.96 93.22,90.42 106.68,90.68 24+2.P$1
N$61
  Top 0.61: 23+2.P$1 94.68,99.67 102.75,99.67 24+2.P$2
N$62
  Top 0.61: 2+2.P$2 64.77,117.09 7+2.P$1
N$63
  Top 0.61: 7+2.P$2 63.5,113.03 60.2,101.85 62.23,98.04 27+2.P$1
N$64
  Top 0.61: 9+2.P$2 77.98,137.92 80.37,138.97 78.49,145.29 77.98,145.8 arc-37 117.35,132.08 120.4,133.86 8+2.P$1
N$65
  Top 0.406: 64.91,89.18 +20+2.P$2
  Top 0.7: 64.91,89.18 R15.1 65.99,86.26 R18.2
N$66
  Top 0.406: R8.1 45.21,55.49 +20.P$2 45.83,57.88 R20.2
N$67
  Top 0.406: 43.94,40.64 +20+3.P$1
  Top 0.61: +19+3.P$2 39.88,40.64 43.94,40.64
N$68
  Top 0.61: 28+3.P$2 23.88,22.86 26.92,19.81 30.23,22.86 33.78,21.84 35.56,27.69 39.12,27.69 +19+3.P$1
N$69
  Top 0.61: 27+3.P$2 arc14 18.54,29.72 23.37,29.72 28+3.P$1
N$70
  Top 0.61: 4+3.P$2 arc9 2.03,71.12 4.83,71.12 4.83,69.85 2+3.P$1
N$71
  Top 0.61: 6+3.P$2 arc14 2.79,87.12 5.08,86.61 4+3.P$1
N$72
  Top 0.61: 0+3.P$2 arc10 6.35,101.85 8.64,101.09 6+3.P$1
N$73
  Top 0.61: 0+3.P$1 14.73,115.57 12.95,115.57 arc-12 5+3.P$2
N$74
  Top 0.61: 5+3.P$1 26.16,121.41 arc21 13.46,99.57 17.78,99.57 18.78,98.82 18.54,98.81 18.78,98.03 3+3.P$2
N$75
  Top 0.61: 1+3.P$2 3+3.P$1
N$76
  Top 0.61: 8+3.P$2 33.78,77.47 25.4,84.07 25.4,87.12 1+3.P$1
N$77
  Top 0.5: 21+3.P$2 33,97.87 33,93 41,93 41,89 41.24,89 9+3.P$1
N$78
  Top 0.61: 21+3.P$1 38.1,99.57 42.93,99.57 22+3.P$2
N$79
  Top 0.61: 23+3.P$2 22+3.P$1
N$80
  Top 0.61: +1+3.P$2 64.77,72.64 +2+3.P$1
N$81
  Top 0.61: +3+3.P$1 +2+3.P$2
N$82
  Top 0.61: +3+3.P$2 49.28,75.18 57.4,78.99 23+3.P$1
N$83
  Top 0.61: 2+3.P$2 arc22 4.83,56.39 7.62,56.39 7.87,55.12 7+3.P$1
N$84
  Top 0.61: 7+3.P$2 arc23 10.41,42.42 13.97,42.42 27+3.P$1
N$85
  Top 0.61: 9+3.P$2 39.62,80.26 8+3.P$1
N$86
  Bottom 0.406: R33.1 98.04,101.85 96.27,103.63 96.27,105.03 R31.1 96.64,109.22 | 96.64,109.22 96.64,109.47 R16.P$2 | D1.A 91.11,115.65 97.54,109.22 96.64,109.22
N$88
  Bottom 0.5: R36.P$1 98.98,57.66 PH1.2 107.81,65.81 112,66 114,68.58 R0A.2
N$91
  Bottom 0.406: R30.2 104.78,105.16 106.43,105.16 107.32,104.26 R32.2 107.32,99.29 R16.P$1 104.78,92.46 82.8,92.46 D3.C 82.55,95.07 D4.C
  Bottom 0.5: 82.8,92.46 75.69,92.37 R2.2
N$92
  Bottom 0.406: 43.66,99.58 43.85,99.39 R22.P$1 45.43,99.84 | R27.2 46.8,101.21 45.81,100.22 45.43,99.84 | 45.43,99.84
  Bottom 0.5: Q5.3 47.24,97.79 45.81,100.22 | R27.2 R26.2
N$93
  Bottom 0.406: 82.8,98.61 D3.A 83.06,98.73 | 83.06,98.73 AC1.P$1 | 83.06,98.73 D6.C
N$94
  Bottom 0.5: Q2.1 67.57,44.24 P4ZD2.C 68.83,46.83 70,48 70,50.42 69.98,50.45 | 69.98,50.45 69.57,50.43 68.5,51.5 67.27,51.5 R13.2 | 69.98,50.45 Q3.3
N$95
  Bottom 0.406: R4.2 96.11,75.61 U$1.P$3
  Bottom 0.5: U$2.4 101.7,69.7 99,67 94.5,67 93,68.5 93,70 92,71 92,74 91.88,74.12 R4.2
N$96
  Bottom 0.5: P4ZD1.C 64.97,85.85 70.36,85.85 71.12,85.09 84.07,85.09 84.71,84.46 C5.2 88.88,84.46 R21.2 | R44.1 87.63,88.81 87.63,84.58 87.73,84.48 R21.2 | R21.2 90.16,84.16 93.5,87.5 105,87.5 | 105,87.5 115.5,87.5 116.8,87.2 arc-39 117.3,65.65 R0A2.2 | R0A1.2 105.05,87.55 105,87.5
N$97
  Bottom 0.5: R2.1 81.87,88.65 R44.2
N$98
  Bottom 0.5: Q1.1 86.17,40.49 R6.1
N$99
  Bottom 0.5: R26.1 R23.2
N$100
  Bottom 0.5: R27.1 R25.2
N$101
  Bottom 0.5: Q1.3 80.95,35.79 R5.2
N$102
  Bottom 0.5: R6.2 89.68,49.32 87,52 87,58 91.56,60.73 | 91.56,60.73 92,61 | R0A4.1 91.5,60.79 91.56,60.73
N$103
  Bottom 0.5: P4ZD3.C 50.4,82.23 Q4.1 45.3,84.09 R24.2
N$104
  Bottom 0.5: R29.1 48.28,94.49 Q5.1 48.19,92.21 P4ZD7.C
N$105
  Bottom 0.5: R5.1 77.98,37.85 | 77.98,37.85 77.98,37.34 | 77.98,37.85 77.98,40.67 | 77.98,40.67 R3.1 | P4ZD2.A 72.23,42.5 Q2.2 76.89,42.39 | 76.89,42.39 77.5,43 77.5,45.2 R9.1 | 77.98,40.67 77.98,41.31 76.89,42.39
N$106
  Bottom 0.5: R7.1 55.27,94.74 R29.2
N$107
  Bottom 0.406: R31.2 R30.1
N$108
  Bottom 0.406: R32.1 102.24,101.6 R33.2
N$109
  Bottom 0.5: Q3.1 75.38,52 79.83,52.05 80.84,51.84 R9.2
N$110
  Bottom 0.406: U$2.1 103.73,75.61 106.02,77.9 U$1.P$5
  Bottom 0.5: R1.1 109.06,81.43 U$1.P$5 112.6,77.9 113.5,77 113.5,75 | 113.5,75 113.5,74.5 | R0A.1 113.91,74.59 113.5,75
N$111
  Bottom 0.5: R0A3.2 109.5,62.5 110,62 R0A2.1
N$112
  Bottom 0.5: U$1.P$8 109.06,67.99 R0A3.1
N$113
  Bottom 0.5: U$2.6 101.7,76.2 106.5,81 R0A1.1 106.5,84.5
N$114
  Bottom 0.5: U$2.3 103.73,63.73 103,65 92.5,65 91.7,65.4 | U$1.P$4 86.9,77.9 86,77 86,72.5 91.5,67 91.5,65.5 91.7,65.4 | R0A4.2 91.5,65.2 91.7,65.4
VDD
  Bottom 0.5: Q4.2 56.75,80.33 C3.+ 58.58,78.5 65.5,78.5 arc79 75.5,68.5 84.5,68.5 | U$1.P$2 96.28,72.9 | 99.5,72.82 U$1.P$2 | 99.5,72.82 U$2.5 | U$1.P$2 | R36.P$3 92.92,50.58 93.5,52 93.5,59 | PH1.1 94.19,59.31 93.5,59 | C1.2 100.54,81.54 100,81 100,80.5 | 100,80.5 100,73.32 99.5,72.82 | 84.5,68.5 84.5,78 85.5,79 87,79 87.5,79.5 92,79.5 93.5,81 99.5,81 100,80.5 | 84.5,68.5 87.5,68.5 89,67 89.5,64.5 90,63 93.5,63 93.75,62.75 | 93.5,59 93.5,60 93.75,62.75 | 93.75,62.75 94,63
VSS
  Bottom 0.5: P4ZD7.A 49.94,86.54 P4ZD3.A 56.55,86.54 C3.- 60.96,82.12 P4ZD1.A 64.97,81.79 69.85,81.79 70.61,82.55 arc-50 80.52,82.55 81.92,81.4 C5.1 88.6,81.66 R21.1 91,82 95,86 102,86 | 102,86 114.5,86 115.5,82.5 115.5,82 | U$1.P$7 U$2.2 | U$1.P$7 | U$1.P$7 109.25,73 116.5,73 | R36.P$2 113,60 113,63.5 115,66.5 116.5,70 116.5,73 | C1.1 101.65,85.65 102,86 | R1.2 111.85,82 115.5,82 | 115.5,82 116.5,81 116.5,73
(copper drawn outside any net)
  shapes: Bottom circle x3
